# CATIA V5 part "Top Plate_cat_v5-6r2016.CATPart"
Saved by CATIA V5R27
Part number: Top Plate
Bounding box of the stored display mesh (mm): x -125 to 125, y 0 to 150, z 180 to 210
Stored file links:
  E:\_Deepak\2017_Deepak\CATIA\Resources\Tutorial Files\Tutorials\c12_catia_v5_6r2015_tut\c12tut2\Top Plate_cat_v5-6r2016.CATPart
  D:\CATIA V5R21 E-RESOURCES\CATIA-V5R21\catia-v5r21-Tut\c12-catia-v5r21-tut\c12-catia-v5r21-tut02\Bush.CATPart
  D:\CATIA V5R21 E-RESOURCES\CATIA-V5R21\catia-v5r21-Tut\c12-catia-v5r21-tut\c12-catia-v5r21-tut02\Bottom Plate.CATPart
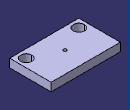
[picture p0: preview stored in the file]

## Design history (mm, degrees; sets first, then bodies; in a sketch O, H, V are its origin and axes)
Set1
  DatumSurface1: linked copy from another document
  DatumCurve1 to DatumCurve5: linked copy from another document
Body1 (main body)
  Sketch1 on face of DatumSurface1, origin (0, 0, 210), H (1, 0, 0), V (0, 1, 0)
    projected line E1 (-125, 0) -> (125, 0) from edge of DatumCurve1
    point P1 (-125, 0)
    point P2 (125, 0)
    projected line E2 (125, 0) -> (125, 150) from edge of DatumCurve2
    point P3 (125, 0)
    point P4 (125, 150)
    projected line E3 (125, 150) -> (-125, 150) from edge of DatumCurve3
    point P5 (125, 150)
    point P6 (-125, 150)
    projected line E4 (-125, 150) -> (-125, 0) from edge of DatumCurve4
    point P7 (-125, 150)
    point P8 (-125, 0)
    projected circle E5 centre (95, 30) radius 20 from edge of DatumCurve5
    circle A1 centre (-95, 30) radius 20
    symmetry: E5 A1 V
    coincidence: P1 P8, P2 P3, P4 P5, P6 P7
  Pad1: profile Sketch1, direction (0, 0, -1), length 30
  Sketch2 on face of Pad1, origin (0, 0, 210), H (1, 0, 0), V (0, 1, 0)
    circle A1 centre (0, 75) radius 6
    point P1 (0, 75)
    reference projected line E1 (-125, 0) -> (125, 0) from edge [face of Pad1 | face of Pad1]
    radius A1 = 6
    distance E1 P1 = 75
    coincidence: P1 V
  Pocket1: profile Sketch2, direction (0, 0, -1), through (limit type 6)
